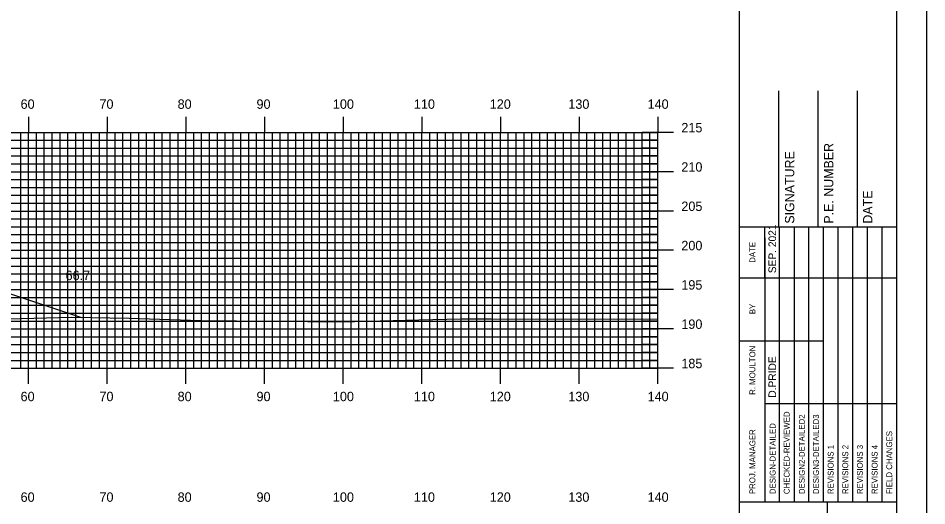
# Model space of a CAD drawing. Extents: x 1815309 to 1815652, y 442591 to 442811.
# Drawn here: x 1815533.2 to 1815648.7, y 442686.2 to 442748.2 of the extents above; entities that cross this region are included whole.
import ezdxf

# ---------------------------------------------------------------- set-up
doc = ezdxf.new("R2010")
doc.units = 0
for name, color, linetype in [('BORDER', 7, 'Continuous'), ('D_Roadway_Centerline', 7, 'Continuous'), ('D_Roadway_SlopeLines', 7, 'Continuous'), ('D_Text_Standard', 7, 'Continuous'), ('H_V ANNOTATION', 7, 'Continuous'), ('MAJOR', 7, 'Continuous'), ('MINOR', 7, 'Continuous'), ('PLOT BOUNDARY', 7, 'Continuous'), ('S_Roadway_Centerline', 7, 'Continuous')]:
    doc.layers.add(name, color=color, linetype=linetype)

msp = doc.modelspace()

# ---------------------------------------------------------------- linework, layer by layer
at = {"layer": 'BORDER'}
for p, q in [((1815624.93, 442596.67), (1815624.93, 442806.67)), ((1815629.93, 442721.67), (1815629.93, 442738.97)), ((1815634.93, 442721.67), (1815634.93, 442738.97)), ((1815639.93, 442721.67), (1815639.93, 442738.97)), ((1815624.93, 442721.67), (1815644.93, 442721.67)), ((1815624.93, 442686.67), (1815644.93, 442686.67)), ((1815636.12, 442616.67), (1815636.12, 442686.67))]:
    msp.add_line(p, q, dxfattribs=at)
msp.add_lwpolyline([(1815324.93, 442596.67), (1815644.93, 442596.67), (1815644.93, 442806.67), (1815324.93, 442806.67)], close=True, dxfattribs=at)
for points in [[(1815628.16, 442715.17), (1815628.16, 442721.67)], [(1815630.03, 442686.68), (1815630.03, 442721.67)], [(1815631.89, 442721.67), (1815631.89, 442686.68)], [(1815633.76, 442686.68), (1815633.76, 442721.67)], [(1815635.62, 442686.68), (1815635.62, 442721.67)], [(1815637.48, 442686.68), (1815637.48, 442721.67)], [(1815639.35, 442686.68), (1815639.35, 442721.67)], [(1815641.21, 442686.68), (1815641.21, 442721.67)], [(1815643.07, 442686.68), (1815643.07, 442721.67)], [(1815628.17, 442686.68), (1815628.17, 442720.26)], [(1815624.93, 442715.17), (1815644.93, 442715.17)], [(1815624.93, 442707.17), (1815628.17, 442707.17)], [(1815628.16, 442707.17), (1815635.62, 442707.17)], [(1815628.16, 442699.17), (1815644.93, 442699.17)]]:
    msp.add_lwpolyline(points, dxfattribs=at)
at = {"layer": 'D_Roadway_Centerline'}
msp.add_lwpolyline([(1815412.84, 442712.11), (1815442.53, 442722.01), (1815444.36, 442722.46), (1815454.53, 442725.01), (1815462.53, 442725.33), (1815474.53, 442725.27), (1815486.53, 442725.03), (1815494.53, 442724.71), (1815504.71, 442722.17), (1815506.53, 442721.71), (1815541.27, 442710.13)], dxfattribs=at)
at = {"layer": 'D_Roadway_SlopeLines'}
msp.add_lwpolyline([(1815494.53, 442724.71), (1815506.53, 442721.71), (1815541.27, 442710.13)], dxfattribs=at)
at = {"layer": 'MAJOR'}
for p, q in [((1815534.53, 442735.67), (1815534.53, 442733.67)), ((1815544.53, 442735.67), (1815544.53, 442733.67)), ((1815554.53, 442735.67), (1815554.53, 442733.67)), ((1815564.53, 442735.67), (1815564.53, 442733.67)), ((1815574.53, 442735.67), (1815574.53, 442733.67)), ((1815584.53, 442735.67), (1815584.53, 442733.67)), ((1815594.53, 442735.67), (1815594.53, 442733.67)), ((1815604.53, 442735.67), (1815604.53, 442733.67)), ((1815614.53, 442735.67), (1815614.53, 442733.67)), ((1815334.53, 442733.67), (1815614.53, 442733.67)), ((1815334.53, 442733.67), (1815614.53, 442733.67)), ((1815534.53, 442703.67), (1815534.53, 442733.67)), ((1815544.53, 442703.67), (1815544.53, 442733.67)), ((1815554.53, 442703.67), (1815554.53, 442733.67)), ((1815564.53, 442703.67), (1815564.53, 442733.67)), ((1815574.53, 442703.67), (1815574.53, 442733.67)), ((1815584.53, 442703.67), (1815584.53, 442733.67)), ((1815594.53, 442703.67), (1815594.53, 442733.67)), ((1815604.53, 442703.67), (1815604.53, 442733.67)), ((1815616.54, 442733.67), (1815612.53, 442733.67)), ((1815614.53, 442703.67), (1815614.53, 442733.67)), ((1815614.53, 442703.67), (1815614.53, 442733.67)), ((1815334.53, 442728.67), (1815614.53, 442728.67)), ((1815616.54, 442728.67), (1815612.53, 442728.67)), ((1815334.53, 442723.67), (1815614.53, 442723.67)), ((1815616.54, 442723.67), (1815612.53, 442723.67)), ((1815334.53, 442718.67), (1815614.53, 442718.67)), ((1815616.54, 442718.67), (1815612.53, 442718.67)), ((1815334.53, 442713.67), (1815614.53, 442713.67)), ((1815616.54, 442713.67), (1815612.53, 442713.67)), ((1815334.53, 442708.67), (1815614.53, 442708.67)), ((1815616.54, 442708.67), (1815612.53, 442708.67)), ((1815334.53, 442703.67), (1815614.53, 442703.67)), ((1815334.53, 442703.67), (1815614.53, 442703.67)), ((1815534.53, 442701.66), (1815534.53, 442703.67)), ((1815544.53, 442701.66), (1815544.53, 442703.67)), ((1815554.53, 442701.66), (1815554.53, 442703.67)), ((1815564.53, 442701.66), (1815564.53, 442703.67)), ((1815574.53, 442701.66), (1815574.53, 442703.67)), ((1815584.53, 442701.66), (1815584.53, 442703.67)), ((1815594.53, 442701.66), (1815594.53, 442703.67)), ((1815604.53, 442701.66), (1815604.53, 442703.67)), ((1815616.54, 442703.67), (1815612.53, 442703.67)), ((1815614.53, 442701.66), (1815614.53, 442703.67))]:
    msp.add_line(p, q, dxfattribs=at)
at = {"layer": 'MINOR'}
for p, q in [((1815533.53, 442703.67), (1815533.53, 442733.67)), ((1815535.53, 442703.67), (1815535.53, 442733.67)), ((1815536.53, 442703.67), (1815536.53, 442733.67)), ((1815537.53, 442703.67), (1815537.53, 442733.67)), ((1815538.53, 442703.67), (1815538.53, 442733.67)), ((1815539.53, 442703.67), (1815539.53, 442733.67)), ((1815540.53, 442703.67), (1815540.53, 442733.67)), ((1815541.53, 442703.67), (1815541.53, 442733.67)), ((1815542.53, 442703.67), (1815542.53, 442733.67)), ((1815543.53, 442703.67), (1815543.53, 442733.67)), ((1815545.53, 442703.67), (1815545.53, 442733.67)), ((1815546.53, 442703.67), (1815546.53, 442733.67)), ((1815547.53, 442703.67), (1815547.53, 442733.67)), ((1815548.53, 442703.67), (1815548.53, 442733.67)), ((1815549.53, 442703.67), (1815549.53, 442733.67)), ((1815550.53, 442703.67), (1815550.53, 442733.67)), ((1815551.53, 442703.67), (1815551.53, 442733.67)), ((1815552.53, 442703.67), (1815552.53, 442733.67)), ((1815553.53, 442703.67), (1815553.53, 442733.67)), ((1815555.53, 442703.67), (1815555.53, 442733.67)), ((1815556.53, 442703.67), (1815556.53, 442733.67)), ((1815557.53, 442703.67), (1815557.53, 442733.67)), ((1815558.53, 442703.67), (1815558.53, 442733.67)), ((1815559.53, 442703.67), (1815559.53, 442733.67)), ((1815560.53, 442703.67), (1815560.53, 442733.67)), ((1815561.53, 442703.67), (1815561.53, 442733.67)), ((1815562.53, 442703.67), (1815562.53, 442733.67)), ((1815563.53, 442703.67), (1815563.53, 442733.67)), ((1815565.53, 442703.67), (1815565.53, 442733.67)), ((1815566.53, 442703.67), (1815566.53, 442733.67)), ((1815567.53, 442703.67), (1815567.53, 442733.67)), ((1815568.53, 442703.67), (1815568.53, 442733.67)), ((1815569.53, 442703.67), (1815569.53, 442733.67)), ((1815570.53, 442703.67), (1815570.53, 442733.67)), ((1815571.53, 442703.67), (1815571.53, 442733.67)), ((1815572.53, 442703.67), (1815572.53, 442733.67)), ((1815573.53, 442703.67), (1815573.53, 442733.67)), ((1815575.53, 442703.67), (1815575.53, 442733.67)), ((1815576.53, 442703.67), (1815576.53, 442733.67)), ((1815577.53, 442703.67), (1815577.53, 442733.67)), ((1815578.53, 442703.67), (1815578.53, 442733.67)), ((1815579.53, 442703.67), (1815579.53, 442733.67)), ((1815580.53, 442703.67), (1815580.53, 442733.67)), ((1815581.53, 442703.67), (1815581.53, 442733.67)), ((1815582.53, 442703.67), (1815582.53, 442733.67)), ((1815583.53, 442703.67), (1815583.53, 442733.67)), ((1815585.53, 442703.67), (1815585.53, 442733.67)), ((1815586.53, 442703.67), (1815586.53, 442733.67)), ((1815587.53, 442703.67), (1815587.53, 442733.67)), ((1815588.53, 442703.67), (1815588.53, 442733.67)), ((1815589.53, 442703.67), (1815589.53, 442733.67)), ((1815590.53, 442703.67), (1815590.53, 442733.67)), ((1815591.53, 442703.67), (1815591.53, 442733.67)), ((1815592.53, 442703.67), (1815592.53, 442733.67)), ((1815593.53, 442703.67), (1815593.53, 442733.67)), ((1815595.53, 442703.67), (1815595.53, 442733.67)), ((1815596.53, 442703.67), (1815596.53, 442733.67)), ((1815597.53, 442703.67), (1815597.53, 442733.67)), ((1815598.53, 442703.67), (1815598.53, 442733.67)), ((1815599.53, 442703.67), (1815599.53, 442733.67)), ((1815600.53, 442703.67), (1815600.53, 442733.67)), ((1815601.53, 442703.67), (1815601.53, 442733.67)), ((1815602.53, 442703.67), (1815602.53, 442733.67)), ((1815603.53, 442703.67), (1815603.53, 442733.67)), ((1815605.53, 442703.67), (1815605.53, 442733.67)), ((1815606.53, 442703.67), (1815606.53, 442733.67)), ((1815607.53, 442703.67), (1815607.53, 442733.67)), ((1815608.53, 442703.67), (1815608.53, 442733.67)), ((1815609.53, 442703.67), (1815609.53, 442733.67)), ((1815610.53, 442703.67), (1815610.53, 442733.67)), ((1815611.53, 442703.67), (1815611.53, 442733.67)), ((1815612.53, 442703.67), (1815612.53, 442733.67)), ((1815613.53, 442703.67), (1815613.53, 442733.67)), ((1815334.53, 442732.67), (1815614.53, 442732.67)), ((1815614.53, 442732.67), (1815612.53, 442732.67)), ((1815334.53, 442731.67), (1815614.53, 442731.67)), ((1815614.53, 442731.67), (1815612.53, 442731.67)), ((1815334.53, 442730.67), (1815614.53, 442730.67)), ((1815334.53, 442729.67), (1815614.53, 442729.67)), ((1815614.53, 442730.67), (1815612.53, 442730.67)), ((1815614.53, 442729.67), (1815612.53, 442729.67)), ((1815334.53, 442727.67), (1815614.53, 442727.67)), ((1815614.53, 442727.67), (1815612.53, 442727.67)), ((1815334.53, 442726.67), (1815614.53, 442726.67)), ((1815614.53, 442726.67), (1815612.53, 442726.67)), ((1815334.53, 442725.67), (1815614.53, 442725.67)), ((1815614.53, 442725.67), (1815612.53, 442725.67)), ((1815334.53, 442724.67), (1815614.53, 442724.67)), ((1815614.53, 442724.67), (1815612.53, 442724.67)), ((1815334.53, 442722.67), (1815614.53, 442722.67)), ((1815334.53, 442721.67), (1815614.53, 442721.67)), ((1815614.53, 442722.67), (1815612.53, 442722.67)), ((1815614.53, 442721.67), (1815612.53, 442721.67)), ((1815334.53, 442720.67), (1815614.53, 442720.67)), ((1815614.53, 442720.67), (1815612.53, 442720.67)), ((1815334.53, 442719.67), (1815614.53, 442719.67)), ((1815614.53, 442719.67), (1815612.53, 442719.67)), ((1815334.53, 442717.67), (1815614.53, 442717.67)), ((1815614.53, 442717.67), (1815612.53, 442717.67)), ((1815334.53, 442716.67), (1815614.53, 442716.67)), ((1815614.53, 442716.67), (1815612.53, 442716.67)), ((1815334.53, 442715.67), (1815614.53, 442715.67)), ((1815334.53, 442714.67), (1815614.53, 442714.67)), ((1815614.53, 442715.67), (1815612.53, 442715.67)), ((1815614.53, 442714.67), (1815612.53, 442714.67)), ((1815334.53, 442712.67), (1815614.53, 442712.67)), ((1815614.53, 442712.67), (1815612.53, 442712.67)), ((1815334.53, 442711.67), (1815614.53, 442711.67)), ((1815614.53, 442711.67), (1815612.53, 442711.67)), ((1815334.53, 442710.67), (1815614.53, 442710.67)), ((1815614.53, 442710.67), (1815612.53, 442710.67)), ((1815334.53, 442709.67), (1815614.53, 442709.67)), ((1815614.53, 442709.67), (1815612.53, 442709.67)), ((1815334.53, 442707.67), (1815614.53, 442707.67)), ((1815334.53, 442706.67), (1815614.53, 442706.67)), ((1815614.53, 442707.67), (1815612.53, 442707.67)), ((1815614.53, 442706.67), (1815612.53, 442706.67)), ((1815334.53, 442705.67), (1815614.53, 442705.67)), ((1815614.53, 442705.67), (1815612.53, 442705.67)), ((1815334.53, 442704.67), (1815614.53, 442704.67)), ((1815614.53, 442704.67), (1815612.53, 442704.67))]:
    msp.add_line(p, q, dxfattribs=at)
at = {"layer": 'PLOT BOUNDARY'}
msp.add_lwpolyline([(1815308.75, 442590.55), (1815648.75, 442590.55), (1815648.75, 442810.55), (1815308.75, 442810.55)], close=True, dxfattribs=at)
at = {"layer": 'S_Roadway_Centerline'}
msp.add_lwpolyline([(1815525.6, 442709.76), (1815539.97, 442710.15), (1815547.31, 442710.04), (1815556.43, 442709.75), (1815570.04, 442709.63), (1815573.72, 442709.62), (1815575.99, 442709.63), (1815584.15, 442709.82), (1815589.5, 442709.96), (1815590.91, 442709.94), (1815593.36, 442709.97), (1815607.46, 442709.9), (1815614.53, 442709.97)], dxfattribs=at)

# ---------------------------------------------------------------- texts
at = {"layer": 'BORDER'}
for s, height, p in [('P.E. NUMBER', 1.1811, (1815636.86, 442722.06)), ('SIGNATURE', 1.181, (1815631.89, 442722.06)), ('DATE', 1.181, (1815641.82, 442722.06)), ('SEP. 2021', 0.969, (1815629.58, 442715.76)), ('DATE', 0.743, (1815626.94, 442717.08)), ('BY', 0.743, (1815626.94, 442710.54)), ('R. MOULTON', 0.745, (1815626.94, 442700.28)), ('D.PRIDE', 0.969, (1815629.58, 442699.92)), ('CHECKED-REVIEWED', 0.7455, (1815631.3, 442687.65)), ('DESIGN2-DETAILED2', 0.7455, (1815633.23, 442687.65)), ('DESIGN3-DETAILED3', 0.7455, (1815635.02, 442687.65)), ('DESIGN-DETAILED', 0.7455, (1815629.51, 442687.65)), ('PROJ. MANAGER', 0.7455, (1815626.94, 442687.65)), ('FIELD CHANGES', 0.7455, (1815644.34, 442687.65)), ('REVISIONS 1', 0.7455, (1815636.89, 442687.65)), ('REVISIONS 2', 0.7455, (1815638.75, 442687.65)), ('REVISIONS 3', 0.7455, (1815640.61, 442687.65)), ('REVISIONS 4', 0.7455, (1815642.48, 442687.65))]:
    msp.add_text(s, height=height, rotation=90, dxfattribs=at).set_placement(p)
at = {"layer": 'D_Text_Standard'}
msp.add_text("66.7'", height=1.2, dxfattribs=at).set_placement((1815539.23, 442714.88))
at = {"layer": 'H_V ANNOTATION'}
for s, p in [('60', (1815533.51, 442736.67)), ('70', (1815543.54, 442736.67)), ('80', (1815553.48, 442736.67)), ('90', (1815563.51, 442736.67)), ('100', (1815573.22, 442736.67)), ('110', (1815583.52, 442736.67)), ('120', (1815593.17, 442736.67)), ('130', (1815603.16, 442736.67)), ('140', (1815613.24, 442736.67)), ('215', (1815617.53, 442733.67)), ('210', (1815617.53, 442728.67)), ('205', (1815617.53, 442723.67)), ('200', (1815617.53, 442718.67)), ('195', (1815617.53, 442713.67)), ('190', (1815617.53, 442708.67)), ('185', (1815617.53, 442703.67)), ('60', (1815533.51, 442699.47)), ('70', (1815543.54, 442699.47)), ('80', (1815553.48, 442699.47)), ('90', (1815563.51, 442699.47)), ('100', (1815573.22, 442699.47)), ('110', (1815583.52, 442699.47)), ('120', (1815593.17, 442699.47)), ('130', (1815603.16, 442699.47)), ('140', (1815613.24, 442699.47)), ('60', (1815533.51, 442686.67)), ('70', (1815543.54, 442686.67)), ('80', (1815553.48, 442686.67)), ('90', (1815563.51, 442686.67)), ('100', (1815573.22, 442686.67)), ('110', (1815583.52, 442686.67)), ('120', (1815593.17, 442686.67)), ('130', (1815603.16, 442686.67)), ('140', (1815613.24, 442686.67))]:
    msp.add_text(s, height=1.2, dxfattribs=at).set_placement(p)

doc.saveas('drawing.dxf')
